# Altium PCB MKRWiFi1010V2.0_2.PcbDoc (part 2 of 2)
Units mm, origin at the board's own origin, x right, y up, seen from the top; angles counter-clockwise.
Board outline 61.5 x 25 mm, 4 copper layers (Top, PWR, MID, Bottom), stack 0.925 mm thick; 118 components, 85 nets, 439 pads, 197 vias.
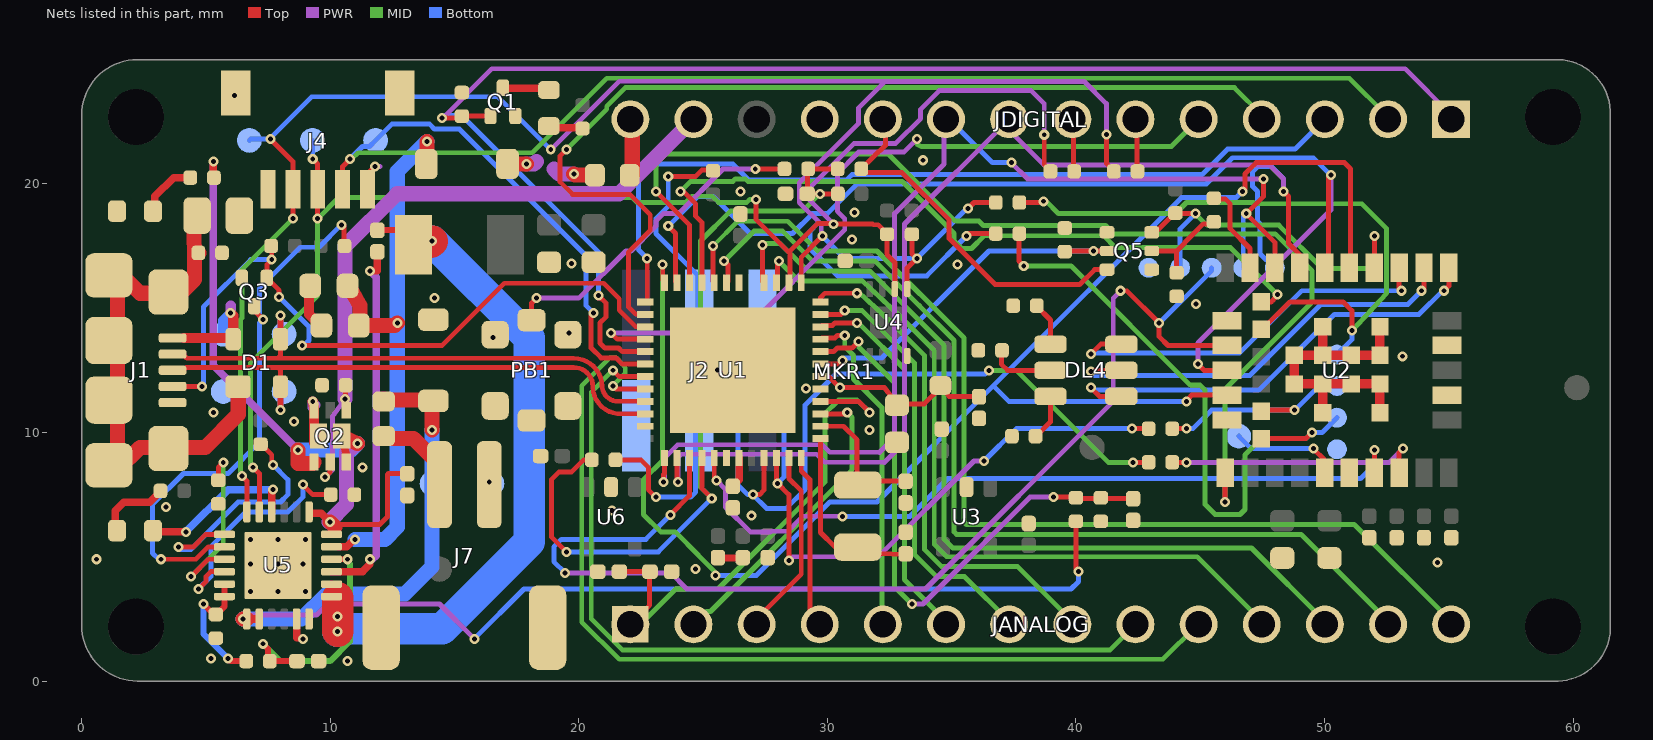
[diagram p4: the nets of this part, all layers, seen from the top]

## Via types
v1: diameter 0.403, hole 0.2, Top to Bottom, tented both sides, 183 vias
v2: diameter 0.398, hole 0.195, Top to Bottom, tented both sides, 14 vias

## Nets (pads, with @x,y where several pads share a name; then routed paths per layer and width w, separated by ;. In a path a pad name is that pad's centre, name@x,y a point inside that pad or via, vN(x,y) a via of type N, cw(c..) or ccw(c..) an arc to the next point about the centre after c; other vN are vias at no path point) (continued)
+5V: D1.4 D3.C F1.2 J1.1 J4.1 Q2.D Q2.D2 VBUS.X | length 10.7
  Top w0.2: J4.1@11.5,19.775 11.5,20.4 v1(11.8,20.7)
  Top w0.406: J1.1@4.125,13.8 5.95,13.8 6.1,13.95 6.1,14.7 v1(6,14.8) ; v2(9.3,11.25) 9.35,11 9.35,10.89 9.35,9.583 Q2.D2@9.533,9.851
  Top w0.61: D3.C@17.105,20.8 v1(17.9,20.8) ; v1(19.8,20.4) 19.85,20.35 F1.2@20.55,20.35
  PWR w0.2: v1(11.8,20.7) v1@12,20.7
  PWR w0.406: v1(6,14.8) 6,15.1 ; v2(9.3,11.25) 9.3,11 v2@9.4,11.1
  PWR w0.61: v1(17.9,20.8) 18.2,20.8 18.3,20.9 ; 19,20.6 19.2,20.4 v1(19.8,20.4)
  Bottom w0.406: VBUS.X@5.7,13.95 5.7,14.5 v1(6,14.8)
GND: BATT-.X C1.2 C2.1 C3.2 C4.2 C5.1 C6.1 C7.1 C8.1 C9.2 C12.1 C13.1 C14.2 C16.2 C17.1 C18.1 C19.1 C20.1 C21.1 C22.1 C23.2 C24.1 C25.2 C26.1 C27.2 C28.2 C29.1 C30.2 C31.1 C32.1 C33.1 D2.A DL3.C GND.X J1.5 J2.5 J4.5 J4.SH1 J4.SH2 J7.2 J7.3 J7.4 JDIGITAL.11 JGND.X MKR1.GND PB1.1 PB1.2 PB1.3 PB1.4 PB1.5 PGND.X Q1.S Q3.S Q5.1 Q5.4 R1.1 R9.1 R10.2 R11.2 R16.1 R19.1 R25.1 R28.2 R29.1 R34.1 R35.1 R36.1 U1.5 U1.18 U1.35 U1.42 U1.49 U2.6 U2.12 U2.14 U2.26 U2.30 U2.GND1 U2.GND2 U2.GND3 U2.GND4 U2.GND5 U2.GND6 U2.GND7 U2.GND8 U2.GND9 U2.GND10 U2.GND11 U2.GND12 U3.2 U4.4 U5.17 U5.18 U5.EXP U6.2 | length 17.2
  Top w0.152: U2.26@45.948,14.627 45.948,14.589 46.037,14.5 U2.26@46.075,14.5
  Top w0.2: v1(19.6,14) 19.625,14.025 PB1.4@19.625,14.075
  Top w0.3: C26.1@25.6,4.951 C24.1@26.6,4.951
  Top w0.305: U5.17@8.65,2.495 8.65,1.75 v1(8.9,1.7)
  Top w0.381: U2.GND7@49.93,10.8 U2.GND8@49.93,11.95 ; U2.GND10@49.93,14.25 U2.GND9@49.93,13.1 ; U2.GND1@52.23,10.8 U2.GND2@52.23,11.95 U2.GND5@51.08,11.95 U2.GND8@49.93,11.95 ; U2.GND4@52.23,14.25 U2.GND3@52.23,13.1 U2.GND6@51.08,13.1 U2.GND9@49.93,13.1 ; U2.GND8@49.93,11.95 U2.GND11@48.78,11.95 U2.GND12@48.78,13.1 U2.GND9@49.93,13.1
  Top w0.406: C13.1@9.25,15.901 9.15,15.801 9.15,14.75 9.6,14.3 C12.1@9.7,14.3
  MID w0.2: 19.4,14.3 19.6,14.1 v1(19.6,14)
  other v1: 10.7,0.8 5.2,0.9 6.8,3.6 7.9,3.6 9,3.6 24.7,4.5 6.8,4.7 7.9,4.7 8.9,4.7 54.535,4.765 0.6,4.9 6.8,5.7 7.9,5.7 9,5.7 26.95,6.65 21.335,6.865 3.4,7 16.4,8 11.3,8.6 31.7,10.1 8.55,10.45 5.3,10.8 29.135,11.765 25.585,12.515 53.135,13.065 16.555,13.815 44.835,15.165 14.2,15.4 35.235,16.765 19.7,16.8 30.985,17.765 31.1,18.85 26.5,19.7 33.85,20.95 6.15,23.55
LED_BLUE: DL4.2 U2.17 | length 17.1
  Top w0.2: v1(40.6,12.45) 40.65,12.5 DL4.2@41.825,12.5 ; v1(53.9,15.7) 54,15.8 U2.17@54,16.625
  Bottom w0.2: v1@40.7,12.35 v1(40.6,12.45) 40.75,12.3 47,12.3 49.85,15.15 53.35,15.15 v1(53.9,15.7)
LED_GREEN: DL4.1 U2.16 | length 18.3
  Top w0.2: v1(40.6,11.8) 40.95,11.45 DL4.1@41.825,11.45 ; v1(54.8,15.7) 55,15.9 U2.16@55,16.625
  Bottom w0.2: v1(40.6,11.8) 40.7,11.7 47.35,11.7 50.4,14.75 53.8,14.75 54.75,15.7 v1(54.8,15.7)
LED_RED: DL4.3 U2.18 | length 15.9
  Top w0.2: v1@40.585,13.135 v1(40.6,13.15) 41,13.55 DL4.3@41.825,13.55 ; U2.18@53,16.625 53,15.8 v1(53.1,15.7)
  Bottom w0.2: v1(40.6,13.15) 40.65,13.2 46.587,13.2 49.088,15.7 v1(53.1,15.7)
NetC1_1: C1.1 D1.1 J1.M1 J1.M2 J1.M3 J1.M4 J1.M5 J1.M6 R1.2 | length 21.2
  Top w0.61: C1.1@4.5,18.725 R1.2@4.55,17.15 ; R1.2@4.725,17.225 R1.2@4.55,17.15 ; D1.1@6.3,11.65 6.3,10.725 4.975,9.4 4,9.4 2.35,9.4 1.45,8.5 1.45,11.3 1.45,13.7 1.45,16.5 2.35,15.6 4,15.6 4.55,16.15 R1.2@4.55,17.15
NetC6_2: C6.2 R8.1 R9.2 U1.8 | length 23.8
  Top w0.2: U1.8@29.725,13.25 30.25,13.25 30.4,13.4 31,13.4 v1(31.25,13.65) ; v1(39.1,7.4) 39.95,7.4 40,7.35 41,7.35 C6.2@42.3,7.35
  PWR w0.2: v1(33.4,3.1) 33.85,3.1 38.15,7.4 v1(39.1,7.4)
  MID w0.2: v1(31.25,13.65) 31.25,13.45 32.7,12 32.7,3.8 v1(33.4,3.1)
NetC14_1: C14.1 Q2.K Q2.K2 Q2.S R27.2 U5.1 U5.24 | length 29
  Top w0.2: U5.1@9.15,6.805 U5.1@9.2,6.755 ; 10.2,6.2 10.3,6.3 10.73,6.3 12,6.3 12.3,6.6 12.3,8.3 12.35,8.35 C14.1@13.1,8.35
  Top w0.3: U5.1@9.2,6.755 9.645,6.755 v1(10,6.4)
  Top w0.305: R27.2@5.3,20.25 v1(5.3,20.9) ; Q2.K2@10.467,9.851 10.65,9.117 Q2.K@10.65,8.81
  Top w0.605: v1(10,6.4) 10.2,6.2
  Top w0.61: v1(8.7,9.3) 8.7,8.75 9.31,8.75 Q2.S@9.35,8.81 ; Q2.K2@10.467,9.851 v1(11.1,9.55)
  PWR w0.305: v1(5.3,20.9) 5.3,12.7 v1(8.7,9.3)
  PWR w0.605: v1(10,6.4) 9.95,6.4 10.65,7.1 10.65,9.2 v1(11.1,9.55)
  Bottom w0.61: v1(8.7,9.3) 10.85,9.3 v1(11.1,9.55)
NetC15_1: C15.1 U5.21 | length 14.8
  Top w0.305: U5.21@10.055,4.4 11.3,4.4 11.6,4.7 v1(11.6,4.9) ; v1(11.6,16.5) 11.9,16.5 C15.1@11.9,17.25
  PWR w0.305: v1(11.6,4.9) 11.7,4.9 11.85,5.05 11.85,16.25 v1(11.6,16.5)
NetC15_2: C15.2 L2.1 U5.19 U5.20 | length 28.4
  Top w0.24: C15.2@11.9,18.15 13.15,18.15 L2.1@13.35,17.55
  Top w0.305: U5.20@10.055,3.9 U5.19@10.055,3.4 10.245,3.4 10.3,3.355 v1(10.3,2.6)
  Top w1.27: v1(10.3,2) U5.19@10.3,3.355 ; L2.1@13.35,17.55 14.05,17.65 v1(14.1,17.7)
  Bottom w1.27: v1(10.3,2) 10.4,2.1 14.5,2.1 18,5.6 18,13.8 v1(14.1,17.7)
NetC16_1: C16.1 R30.1 U5.22 | length 10
  Top w0.24: v1(7.3,1.5) 7.5,1.3 7.5,0.85 7.55,0.8 C16.1@8.65,0.8 ; U5.22@10.055,4.9 v1(10.7,4.9)
  MID w0.24: v1(7.3,1.5) 8,0.8 10,0.8 10.8,1.6 10.8,4.7 10.7,4.8 v1(10.7,4.9)
NetC23_1: C23.1 C27.1 L3.2 U1.6 | length 7.3
  Top w0.2: U1.6@29.725,12.25 30.05,12.25 v1(30.5,11.8) 32.3,11.8 32.8,11.15 33.9,11.15 34.55,11.8 34.9,11.45 C23.1@36.1,11.45
NetC25_1: C25.1 U1.43 | length 1.2
  Top w0.305: C25.1@26.2,7.85 26.45,8.1 U1.43@26.45,8.975
NetDL1_A: DL1.A R15.2 | length 1.4
  Top w0.305: DL1.A@18.8,22.25 R15.2@20.15,22.25
NetDL1_C: DL1.C Q1.D | length 1.9
  Top w0.305: Q1.D@16.95,23.87 16.97,23.85 DL1.C@18.8,23.85
NetDL2_A: DL2.A R23.1 | length 3
  Top w0.305: DL2.A@1.35,6.05 1.35,6.85 1.7,7.2 2.75,7.2 R23.1@3.2,7.65
NetDL3_A: DL3.A R27.1 | length 2.5
  Top w0.305: DL3.A@3.05,18.9 2.95,18.9 2.95,19.5 3.7,20.25 R27.1@4.4,20.25
NetDL4_4: DL4.4 R36.2 | length 1.8
  Top w0.2: R36.2@38.4,15.1 38.975,14.525 DL4.4@38.975,13.55
NetDL4_5: DL4.5 R34.2 | length 2.6
  Top w0.2: R34.2@37,13.3 37,12.75 37.25,12.5 DL4.5@38.975,12.5
NetDL4_6: DL4.6 R35.2 | length 1.8
  Top w0.2: R35.2@38.4,9.85 38.975,10.425 DL4.6@38.975,11.45
NetF1_1: F1.1 JDIGITAL.14 MKR1.5V | length 2.3
  Top w0.61: JDIGITAL.14@22.135,22.66 22.15,22.645 F1.1@22.15,20.35
NetF2_1: F2.1 J7.1 | length 3.5
  Top w0.61: F2.1@12.15,9.75 13.35,9.75 14.4,8.7 J7.1@14.4,7.901
NetJ2_3: J2.3 R2.1 | length 7.2
  Top w0.2: R2.1@21.45,8.9 22.5,8.9 22.8,8.6 22.8,7.7 v1(23.1,7.4)
  Bottom w0.2: v1(23.1,7.4) 24.5,7.4 24.7,7.6 24.7,10.127 J2.3@24.85,10.278
NetJCLK_X: JCLK.X R18.1 U2.35 | length 26.6
  Top w0.2: R18.1@37.7,19.25 38.65,19.25 v1(38.7,19.3) ; U2.35@47.45,14.15 47.5,14.15 48.6,15.25 50.75,15.25 51.1,14.9 v1(51.1,14.1)
  MID w0.2: v1(38.7,19.3) 38.8,19.3 39.3,18.8 44,18.8 44.45,19.25 47.15,19.25 47.2,19.2 51.5,19.2 52.5,18.2 52.5,15.6 v1(51.1,14.1)
  Bottom w0.2: JCLK.X@50.5,13.135 51.1,13.735 v1(51.1,14.1)
NetJDIGITAL_6: JDIGITAL.6 MKR1.11 R31.1 | length 2.2
  Top w0.2: R31.1@42.45,20.5 42.45,22.655 JDIGITAL.6@42.455,22.66
NetJDIGITAL_7: JDIGITAL.7 MKR1.12 R32.1 | length 2.2
  Top w0.2: R32.1@39.9,20.5 39.9,22.645 JDIGITAL.7@39.915,22.66
NetJTDO_X: JTDO.X R22.2 U2.32 | length 8.7
  Top w0.2: R22.2@43.85,10.15 v1(44.45,10.15) ; U2.32@47.45,10.85 47.5,10.9 v1(48.8,10.9)
  Bottom w0.2: v1(44.45,10.15) 44.7,10.15 45.45,10.9 v1(48.8,10.9) 49.765,11.865 JTDO.X@50.5,11.865
NetJTMS_X: JTMS.X R20.1 U2.31 | length 25.9
  Top w0.2: R20.1@37.7,18 37.7,16.9 v1(37.9,16.7) ; U2.31@47.45,9.75 49.25,9.75 v1(49.5,10)
  MID w0.2: v1(37.9,16.7) 39.8,16.7 44.6,11.9 45,11.9 45.2,11.7 45.2,7.1 45.6,6.7 46.6,6.7 46.8,6.9 46.8,9.1 47.45,9.75 49.25,9.75 v1(49.5,10)
  Bottom w0.2: v1(49.5,10) 49.905,10 JTMS.X@50.5,10.595
NetLPO_IN_X: LPO_IN.X U2.5 | length 4.4
  Top w0.2: v1(49.55,9.35) 50,8.9 U2.5@50,8.375
  Bottom w0.2: LPO_IN.X@46.55,9.85 47.05,9.35 v1(49.55,9.35)
NetPB1_6: PB1.6 R3.1 | length 13.2
  Top w0.2: PB1.6@18.1,14.575 18.1,15.2 v1(18.3,15.4) ; v1(27.1,20.6) R3.1@28.3,20.6
  PWR w0.2: v1(18.3,15.4) 20,15.4 21.9,17.3 22.1,17.3 23.1,18.3 23.1,18.5 23.4,18.8 24,18.8 25.8,20.6 v1(27.1,20.6)
NetQ3_D: Q3.D R26.2 U5.8 | length 22.8
  Top w0.2: v1(3.2,4.9) 4.6,4.9 5.1,5.4 U5.8@5.745,5.4 ; Q3.D@6.95,15.081 6.95,14.9 v1(7.3,14.55) ; v1(10.45,18.35) 10.55,18.3 R26.2@10.55,17.5
  Bottom w0.2: v1(3.2,4.9) 3.1,4.9 2.85,5.15 2.85,7.1 4.1,8.35 5.9,8.35 7.15,9.6 7.15,14.4 v1(7.3,14.55) 7.15,14.7 7.15,15.8 8.8,17.45 9.55,17.45 v1(10.45,18.35)
NetQ5_5: Q5.5 R11.1 R17.2 | length 3.9
  Top w0.2: Q5.5@43.05,17.3 44.05,17.3 ; R11.1@44.05,16.4 44.05,17.3 ; R17.2@45.55,18.475 45.468,18.393 45.125,18.393 44.717,17.985 44.383,17.651 44.383,17.633 44.05,17.3
NetQ5_6: Q5.6 R7.1 RST.X U2.19 | length 15.2
  Top w0.2: Q5.6@43.05,18.05 43.2,18.05 R7.1@44,18.85 ; R7.1@43.92,18.77 R7.1@44,18.85 ; v1(44.8,18.8) 44.05,18.8 R7.1@44,18.85 ; U2.19@52,16.625 v1(52,17.9)
  MID w0.2: v1(44.8,18.8) 45.263,18.338 48.162,18.338 49.9,16.6 51.8,16.6 52,16.8 v1(52,17.9)
  Bottom w0.2: RST.X@44.19,16.625 44.19,18.19 v1(44.8,18.8)
NetR12_2: R12.2 U2.8 | length 10.6
  Top w0.2: R12.2@43.85,8.8 v1(44.45,8.8) ; U2.8@53,8.375 53,9.2 v1(53.15,9.35)
  PWR w0.2: v1(44.45,8.8) 52.6,8.8 v1(53.15,9.35)
NetR17_1: R17.1 U2.24 | length 3.6
  Top w0.2: R17.1@45.55,19.4 46,19.4 46.2,19.2 46.2,18.2 47,17.4 U2.24@47,16.625
NetR24_2: R24.2 U5.7 | length 10
  Top w0.2: v1(3.9,5.4) 4.5,5.4 5,5.9 U5.7@5.745,5.9 ; R24.2@7.2,9.55 7.65,9.1 7.65,8.75 v1(7.7,8.7)
  Bottom w0.19: v1(7.7,8.7) v1@7.75,8.75
  Bottom w0.2: v1(3.9,5.4) 4,5.3 4.4,5.3 6.3,7.2 8,7.2 8.3,7.5 8.3,8.1 v1(7.7,8.7)
NetR25_2: R25.2 U5.9 | length 7.6
  Top w0.2: v1(4.4,4.2) 5.1,4.9 U5.9@5.745,4.9 ; R25.2@5.5,8.05 5.5,8.6 v1(5.7,8.8)
  MID w0.2: v1(4.4,4.2) 5.7,5.5 v1(5.7,8.8)
NetR28_1: R28.1 U5.10 | length 9.7
  Top w0.2: v1(4.7,3.7) 5,4 5,4.2 5.2,4.4 U5.10@5.745,4.4 ; v1(8.9,7.9) 9.3,7.5 R28.1@10.05,7.5
  Bottom w0.2: v1(4.7,3.7) 5.2,4.2 5.2,5.4 6.6,6.8 8.3,6.8 8.9,7.4 v1(8.9,7.9)
NetR29_2: R29.2 R30.2 U5.11 U5.12 | length 5.5
  Top w0.24: v1(4.9,3.1) 5.35,2.65 5.4,2.65 5.745,2.995 U5.12@5.745,3.4 U5.11@5.745,3.9 ; v1(5.9,0.9) 6,0.8 R30.2@6.65,0.8
  Bottom w0.24: v1(4.9,3.1) 4.9,1.9 v1(5.9,0.9)
PA00_XIN32: C3.1 U1.1 Y1.2 | length 7.5
  Top w0.2: U1.1@29.725,9.75 29.725,5.975 30.3,5.4 31.213,5.4 Y1.2@31.225,5.387 31.462,5.15 C3.1@33.15,5.1
PA01_XOUT32: C4.1 U1.2 Y1.1 | length 5.5
  Top w0.2: U1.2@29.725,10.25 30.65,10.25 31.2,9.7 31.2,8.612 Y1.1@31.225,7.887 31.388,8.05 C4.1@33.15,8.05
PA02_AIN0: JANALOG.2 MKR1.A0 U1.3 | length 12.4
  Top w0.2: U1.3@29.725,10.75 30.75,10.75 v1(30.8,10.8)
  MID w0.2: JANALOG.2@24.675,2.34 25.135,2.8 25.3,2.8 31,8.5 31,10.6 v1(30.8,10.8)
PA03_VREFA: C5.2 C7.2 JANALOG.1 MKR1.AREF U1.4 | length 20.8
  Top w0.2: C7.2@21.65,4.4 22.85,4.4 22.85,3.055 JANALOG.1@22.135,2.34 ; U1.4@29.725,11.25 31.25,11.25 v1(31.7,10.8)
  MID w0.2: JANALOG.1@22.135,2.34 22.2,2.405 22.605,2.405 23.9,3.7 25.6,3.7 29.9,8 29.9,10.75 30.45,11.3 31.2,11.3 v1(31.7,10.8)
PA04_AIN4: JANALOG.5 MKR1.A3 U1.9 | length 13.3
  Top w0.2: U1.9@29.725,13.75 29.775,13.8 30.3,13.8 30.4,13.9 v1(30.7,13.9)
  MID w0.2: v1(30.7,13.9) 30.7,13.45 31.05,13.1 31.05,12.15 32.2,11 32.2,2.4 32.205,2.395 32.295,2.395 JANALOG.5@32.295,2.34
PA05_AIN5: JANALOG.6 MKR1.A4 U1.10 | length 15.2
  Top w0.2: U1.10@29.725,14.25 29.775,14.3 30.2,14.3 30.3,14.4 v1(31.2,14.4)
  MID w0.2: v1(31.2,14.4) 31.3,14.4 31.3,14.35 33.1,12.55 33.1,4.075 JANALOG.6@34.835,2.34
PA06_AIN6: JANALOG.7 MKR1.A5 U1.11 | length 17.4
  Top w0.2: U1.11@29.725,14.75 30.55,14.75 v1(30.7,14.9)
  MID w0.2: v1(30.7,14.9) 31.4,14.9 33.5,12.8 33.5,5.1 34.4,4.2 35.515,4.2 JANALOG.7@37.375,2.34
PA07_AIN7: JANALOG.8 MKR1.A6 U1.12 | length 20.5
  Top w0.2: U1.12@29.725,15.25 29.725,15.425 29.9,15.6 v1(31.2,15.6)
  MID w0.2: v1(31.2,15.6) 31.3,15.6 32.5,14.5 33.9,13.1 33.9,5.3 34.6,4.6 37.655,4.6 JANALOG.8@39.915,2.34
PA08_S0_I2C_SDA: ESDA.X J4.4 R14.1 R18.2 R31.2 U1.13 U4.5 U5.6 | length 77.7
  Top w0.2: v1(6.45,8.25) 6.65,8.05 U5.6@6.65,6.805 ; v1(7.6,21.8) 8.5,20.9 v1(8.5,18.6) ; U1.13@28.95,16.025 28.95,17.05 v1(29.8,17.9) ; U4.5@33.213,15.95 33.213,16.613 v1(33.6,17) ; R14.1@33.4,18.05 33.4,17.2 v1(33.6,17) ; v1@33.613,16.988 v1(33.6,17) ; v1(35.65,19) 35.9,19.25 R18.2@36.8,19.25 ; v1(41.225,21.988) 41.225,20.825 R31.2@41.55,20.5
  PWR w0.19: v2(18.875,21.375) 21.625,24.125 32.25,24.125 32.263,24.062 ; v1(29.8,17.9) 29.75,18 29.75,18.375 28.875,19.25 28.875,20.045 31.25,22.42 31.25,23.05 32.263,24.062 ; 32.325,24.125 32.263,24.062
  PWR w0.2: 32.325,24.125 40.325,24.125 41.225,23.225 v1(41.225,21.988)
  MID w0.2: v1(6.45,8.25) 6.4,8.3 6.4,14.55 6.45,14.6 6.45,16.55 v1(8.5,18.6)
  Bottom w0.19: v1(7.6,21.8) 7.625,21.875 9.25,23.5 16.75,23.5 v2(18.875,21.375)
  Bottom w0.2: ESDA.X@6.75,21.75 6.8,21.8 v1(7.6,21.8) ; v1(29.8,17.9) 30.7,17 v1(33.6,17) 35.6,19 v1(35.65,19)
PA09_S0_I2C_SCL: ESCL.X J4.3 R13.1 R20.2 R32.2 U1.14 U4.6 U5.5 | length 72.1
  Top w0.19: v2@27.125,19.25 v2(27.125,19.375) ; v2@30.25,18.4 v2(30.25,18.375) 30.26,18.385 31.83,18.385 31.858,18.357 32.043,18.357 32.35,18.05 R13.1@32.4,18.05
  Top w0.2: v1(6.9,8.6) 7.15,8.35 U5.5@7.15,6.805 ; v1(9.3,21) 9.5,20.8 v1(9.5,18.6) ; v2@27.125,19.25 27.125,18.575 28.45,17.25 ; v2@30.25,18.4 29.6,18.4 28.45,17.25 ; R13.1@32.4,18.05 32.4,17.15 32.712,16.837 U4.6@32.712,15.95 ; v1(35.6,17.9) 35.7,18 R20.2@36.8,18 ; v1(38.725,21.975) 38.725,20.775 R32.2@39,20.5 ; 28.45,17.25 28.5,17.2 U1.14@28.5,16.075 ; U1.14@28.5,16.075 U1.14@28.45,16.025 28.475,16.025 28.5,16.05 U1.14@28.5,16.075
  PWR w0.19: v2(30.25,18.375) 29.25,19.375 29.25,19.8 31.075,21.625 32.75,21.625 33.75,22.625 33.75,23 34.5,23.75
  PWR w0.2: 34.5,23.75 38.2,23.75 38.725,23.225 v1(38.725,21.975)
  MID w0.19: 24.55,19.5 25.375,19.5 25.625,19.25 26.75,19.25 26.875,19.375 v2(27.125,19.375)
  MID w0.2: v1(6.9,8.6) 6.8,8.7 6.8,12.8 9.5,15.5 v1(9.5,18.6) 10.35,19.45 22.15,19.45 22.35,19.25 24.3,19.25 24.55,19.5
  Bottom w0.2: ESCL.X@9.29,21.75 9.3,21.74 v1(9.3,21) ; v2(30.25,18.375) 30.225,18.4 29.6,18.4 29.3,18.1 29.3,17.4 30.4,16.3 34,16.3 v1(35.6,17.9)
PA10_TCC0-W2: JANALOG.11 MKR1.2 U1.15 | length 31.1
  Top w0.2: U1.15@27.95,16.025 28,16.075 28,16.85 v1(28.05,16.9)
  PWR w0.2: JANALOG.11@47.5,2.375 JANALOG.11@47.535,2.34
  MID w0.2: v1(28.05,16.9) 28.85,16.1 31.4,16.1 32.9,14.7 34.3,13.3 34.3,5.5 34.8,5 44.875,5 47.535,2.34 JANALOG.11@47.5,2.375
PA11_TCC0-W3: JANALOG.12 MKR1.3 U1.16 | length 35.1
  Top w0.2: v1(27.4,17.55) 27.4,16.075 U1.16@27.45,16.025
  MID w0.2: v1(27.4,17.55) 27.5,17.6 28.1,17.6 29.2,16.5 31.7,16.5 34.7,13.5 34.7,5.7 35.05,5.35 47.065,5.35 JANALOG.12@50.075,2.34
PA12_S2_TX/MOSI: U1.21 U2.36 | length 31.6
  Top w0.2: v1(24.1,19.7) 24.2,19.7 24.7,19.2 24.7,18.7 24.95,18.45 U1.21@24.95,16.025 ; U2.36@47.45,15.25 47.85,15.25 47.9,15.3 v1(48.1,15.55)
  MID w0.2: v1(24.1,19.7) 24.5,20.1 26.2,20.1 26.3,20.2 26.7,20.2 26.8,20.1 33,20.1 35.1,18 35.1,17.7 35.4,17.4 35.8,17.4 36.313,17.913 41.112,17.913 41.587,17.438 46.213,17.438 v1(48.1,15.55)
PA13_S2_RX/MISO: U1.22 U2.1 | length 45.8
  Top w0.2: v1(23.1,19.7) 24.45,18.35 U1.22@24.45,16.025 ; v1(46,7.2) U2.1@46,8.375
  MID w0.2: v1(23.1,19.7) 23.1,20.8 23.5,21.2 32.45,21.2 35.15,18.5 36.1,18.5 36.275,18.325 41.188,18.325 41.525,17.988 48.013,17.988 49.5,16.5 49.5,15.25 46,11.75 v1(46,7.2)
PA14_S2_RTS/CS: U1.23 U2.21 U2.28 | length 46.7
  Top w0.2: v1(23.6,18.3) 23.9,18 23.9,16.075 U1.23@23.95,16.025 ; v1(44.9,12.75) 45.15,12.5 U2.28@46.075,12.5 ; U2.21@50,16.625 50.15,16.775 50.15,20.25 v1(50.25,20.35)
  PWR w0.2: v1(44.9,12.75) 44.9,13.6 50.25,18.95 v1(50.25,20.35)
  Bottom w0.2: v1(23.6,18.3) 24.8,19.5 25.4,19.5 26.9,18 28.6,18 29.4,18.8 30,18.8 31.2,20 45.25,20 46.3,21.05 49.55,21.05 v1(50.25,20.35)
PA15_S2_CTS/SCK: U1.24 U2.20 U2.29 | length 61.8
  Top w0.19: v2(23.375,16.75) 23.375,16.125 U1.24@23.45,16.025
  Top w0.2: v1(44.45,11.25) 44.65,11.5 U2.29@46.075,11.5 ; v1(46.7,19.7) 46.8,19.8 46.8,20.4 47.25,20.85 50.8,20.85 51.05,20.6 51.05,16.675 U2.20@51,16.625
  MID w0.19: 24.825,5.05 25.5,4.375 v2(25.5,4.25)
  MID w0.2: v2(23.375,16.75) 23.375,8.875 22.6,8.1 22.6,6.7 23.3,6 23.875,6 24.825,5.05
  Bottom w0.2: v2(25.5,4.25) 27.15,4.25 30.1,7.2 32,7.2 36.675,11.875 ; v1(44.45,11.25) 37.3,11.25 36.675,11.875 ; v1(46.7,19.7) 46.45,19.45 44.25,19.45 36.675,11.875
PA16_S1_MOSI: JDIGITAL.3 MKR1.8 U1.25 | length 34.5
  Top w0.19: U1.25@22.675,15.25 22.75,15.25 v2(22.75,17)
  PWR w0.19: JDIGITAL.3@50,22.625 JDIGITAL.3@50.075,22.66
  Bottom w0.19: 30.75,20.15 31,20.375
  Bottom w0.2: v2(22.75,17) 22.4,17.35 22.4,20.2 23,20.8 26.2,20.8 26.85,20.15 30.75,20.15 ; 31,20.375 45.075,20.375 46.1,21.4 48.815,21.4 JDIGITAL.3@50.075,22.66
PA17_S1_SCK: JDIGITAL.4 MKR1.9 U1.26 | length 40.1
  Top w0.19: v2(19.5,21.375) 19.25,21.125 19.25,20.075 19.75,19.575 22.05,19.575 22.875,18.75 22.875,18.125 22,17.25 22,15.05 22.3,14.75 U1.26@22.675,14.75
  MID w0.19: v2(19.5,21.375) 21.125,23 21.125,23.125 21.875,23.875 46.375,23.875 47.5,22.75 JDIGITAL.4@47.535,22.66
PA18_OTG: J1.4 Q3.G R21.2 U1.27 | length 28.4
  Top w0.19: v2(8.875,13.5) 14.5,13.5 17,16 21,16 21.625,15.375 21.625,14.925 22.3,14.25 U1.27@22.675,14.25
  Top w0.2: J1.4@4.125,11.85 4.886,11.855 v1(4.849,11.847) ; R21.2@7.65,17.5 v1(7.65,16.95) 7.45,16.75 Q3.G@7.45,16.221 7.95,15.72 v1(7.95,15.45)
  Bottom w0.19: v1@4.824,11.822 v1(4.849,11.847)
  Bottom w0.2: v1(4.849,11.847) 4.897,11.847 4.9,11.85 4.899,12.743 4.899,15.049 6.8,16.95 v1(7.65,16.95) ; v1(7.95,15.45) 9.15,14.25 9.15,13.7 8.95,13.5 v2(8.875,13.5) v2@8.9,13.5
PA19_S1_MISO: JDIGITAL.5 MKR1.10 U1.28 | length 30.9
  Top w0.2: v1(21.3,14) 21.55,13.75 U1.28@22.675,13.75
  PWR w0.2: v1(21.3,14) 26.55,14 30.7,18.15 30.7,18.6 30.4,18.9 30.4,20.4 31.25,21.275 33.075,21.275 v1(33.6,21.8)
  MID w0.2: v1(33.6,21.8) 33.6,21.6 33.8,21.5 43.835,21.5 JDIGITAL.5@44.995,22.66
PA20_TCC0-W6: JDIGITAL.1 MKR1.6 Q1.G R16.2 U1.29 | length 58.9
  Top w0.2: v1(14.5,22.65) 15.25,22.65 15.3,22.75 15.32,22.73 Q1.G@16.45,22.73 ; v1@20.8,15.4 v1(20.8,15.5) 20.85,15.45 21.1,15.2 21.1,14.65 20.85,14.4 20.85,13.6 21.05,13.4 21.6,13.4 21.75,13.25 U1.29@22.675,13.25
  PWR w0.19: v1(14.5,22.65) 14.5,22.625 16.5,24.625 53.25,24.625 55.125,22.75 JDIGITAL.1@55.155,22.66
  Bottom w0.2: v1(14.5,22.65) 14.6,22.75 15.3,22.75 20.8,17.25 v1(20.8,15.5)
PA21_TCC0-W7: EWK.X J4.2 JDIGITAL.2 MKR1.7 U1.30 | length 63.7
  Top w0.2: J4.2@10.5,19.775 10.5,20.7 v1(10.8,21) ; v1(20.6,14.8) 20.5,14.7 20.5,13.4 20.9,13 21.5,13 21.75,12.75 U1.30@22.675,12.75
  MID w0.19: v1(10.8,21) 10.875,21 11.125,21.25 18.125,21.25 21.125,24.25 51,24.25 52.5,22.75 JDIGITAL.2@52.615,22.66
  Bottom w0.2: v1(10.8,21) 11.3,21.5 11.58,21.5 11.83,21.75 12.48,22.4 14,22.4 14.2,22.2 15.2,22.2 20.3,17.1 20.3,15.1 v1(20.6,14.8)
PA22_TC4-W0: JANALOG.9 MKR1.0 U1.31 | length 34.7
  Top w0.19: v2(21.375,12.5) 21.625,12.25 U1.31@22.675,12.25
  MID w0.19: v2(21.375,12.5) 20.5,11.625 20.5,2.5 21.75,1.25 41.375,1.25 42.375,2.25 JANALOG.9@42.455,2.34
PA23_TC4-W1: JANALOG.10 MKR1.1 U1.32 | length 40.3
  Top w0.19: v2(21.375,11.875) 21.5,11.75 U1.32@22.675,11.75
  MID w0.19: v2(21.375,11.875) 21.875,12.375 21.875,12.625 21.5,13 21.25,13 20.125,11.875 20.125,2.375 21.625,0.875 43.5,0.875 44.875,2.25 JANALOG.10@44.995,2.34
PA27_GPIO0: GPIO0.X U1.39 U2.27 | length 47.8
  Top w0.2: v1(23.688,6.688) 24.45,7.45 U1.39@24.45,8.975 ; v1(41.8,15.7) 42.05,15.7 v1(43.35,14.4) ; v1@43.3,14.45 v1(43.35,14.4) ; U2.27@46.075,13.5 43.7,13.5 43.35,13.85 v1(43.35,14.4)
  PWR w0.2: v1(19.45,4.35) 23.7,4.35 24.35,3.7 33.95,3.7 41.5,11.25 41.5,15.4 v1(41.8,15.7) ; v1@43.3,14.45 v1(43.35,14.4)
  Bottom w0.2: v1(19.45,4.35) 19,4.8 19,5.4 19.3,5.7 22.7,5.7 v1(23.688,6.688) ; v1(43.35,14.4) 45.46,16.51 GPIO0.X@45.46,16.625
PA28_ACK: U1.41 U2.7 | length 31.3
  Top w0.19: U1.41@25.45,8.975 25.45,8.175 v1(25.55,8.075)
  Top w0.2: U2.7@52,8.375 v1(52,9.3)
  PWR w0.19: v1(25.55,8.075) 25.9,7.725 25.9,7.125 ; 27.025,6 27.725,6 27.75,6.025 28.4,6.025 29,6.625 v1(30.6,6.625)
  PWR w0.2: 25.9,7.125 25.9,7 26.9,6 27.025,6
  Bottom w0.2: v1(30.6,6.625) 33.325,6.625 34.85,8.15 51.45,8.15 52,8.7 v1(52,9.3)
PA30_SWCLK: J2.4 R4.1 R12.1 U1.45 | length 40.5
  Top w0.19: 27.275,7.5 27.45,7.675 U1.45@27.45,8.975
  Top w0.2: v1(23.6,20.3) 24.7,20.3 24.95,20.55 R4.1@25.4,20.55 ; v1(27,7.5) 27.275,7.5 ; v1(42.3,8.8) R12.1@42.95,8.8
  MID w0.2: v1(36.5,12.5) 37.6,12.5 41.3,8.8 v1(42.3,8.8)
  Bottom w0.2: v1(23.6,20.3) 23.6,19.1 23.1,18.6 23.1,18 24.8,16.3 24.8,14.772 24.85,14.723 26.4,13.172 26.4,7.9 26.8,7.5 v1(27,7.5) 27.55,6.95 28.35,6.95 29.1,7.7 29.1,11.1 30.35,12.35 36.35,12.35 v1(36.5,12.5)
PA31_SWDIO: J2.2 R22.1 U1.46 | length 28.3
  Top w0.2: U1.46@27.95,8.975 27.95,7.95 v1(28,7.95) 28.45,7.5 v1(28.45,4.85) ; v1(42.25,10.15) R22.1@42.95,10.15
  PWR w0.2: v1(28.45,4.85) 28.6,5 32.05,5 35.9,8.85 v1(36.3,8.85)
  Bottom w0.2: J2.2@27.39,14.723 28.25,13.863 28.25,8.2 v1(28,7.95) ; v1(36.3,8.85) 37.6,10.15 v1(42.25,10.15)
PB02_AIN10: JANALOG.3 MKR1.A1 U1.47 | length 7.6
  Top w0.2: JANALOG.3@27.215,2.34 27.215,2.565 28.95,4.3 28.95,7.65 28.45,8.15 U1.47@28.45,8.975
PB03_AIN11: JANALOG.4 MKR1.A2 U1.48 | length 7
  Top w0.2: U1.48@28.95,8.975 28.95,8.45 29.3,8.1 29.3,2.795 JANALOG.4@29.755,2.34
PB08_RST: Q5.2 R10.1 U1.7 | length 14.6
  Top w0.2: U1.7@29.725,12.75 30.45,12.75 v1(30.6,12.9) ; R10.1@39.55,17.3 v1(40.7,17.3) Q5.2@41.25,17.3
  Bottom w0.2: v1(30.6,12.9) 30.7,13 32.2,13 36.5,17.3 v1(40.7,17.3)
PB10_TCC0-W4: JANALOG.13 MKR1.4 U1.19 | length 39.3
  Top w0.19: U1.19@25.95,16.025 U1.19@26,16.075
  Top w0.2: v1(25.85,16.9) 26,16.75 U1.19@26,16.075
  MID w0.19: 27.2,18.1 28.2,18.1 29.4,16.9 31.9,16.9 33.7,15.1
  MID w0.2: v1(25.85,16.9) 27.05,18.1 27.2,18.1 ; 33.7,15.1 35.1,13.7 35.1,6 35.2,5.9 49.055,5.9 JANALOG.13@52.615,2.34
PB11_TCC0-W5: JANALOG.14 MKR1.5 U1.20 | length 42.7
  Top w0.19: v1(25.4,17.5) 25.4,16.075 U1.20@25.45,16.025
  MID w0.19: v1(25.4,17.5) 26.4,18.5 28.4,18.5 29.6,17.3
  MID w0.2: 29.6,17.3 32,17.3 35.5,13.8 35.5,6.4 35.6,6.3 51.195,6.3 JANALOG.14@55.155,2.34
PB22_S5_TX: JDIGITAL.9 MKR1.14 RXD.X U1.37 U2.23 | length 45.9
  Top w0.2: v1(23.4,8) 23.4,8.3 23.45,8.35 U1.37@23.45,8.975 ; v1(47.55,20.2) 47.55,19.5 v1(46.85,18.8) 48,17.65 U2.23@48,16.625
  PWR w0.19: v1(23.4,8) 23.45,8.05 23.45,8.975 23.975,9.5 29.8,9.5 30.1,9.2 32.1,9.2
  PWR w0.2: 32.1,9.2 32.7,9.8 32.7,18.8 34.7,20.8 34.7,22.525 JDIGITAL.9@34.835,22.66 ; v1(37.4,20.85) 38.05,20.2 v1(47.55,20.2)
  Bottom w0.2: JDIGITAL.9@34.835,22.66 36.645,20.85 v1(37.4,20.85) ; RXD.X@46.73,16.625 46.73,18.68 v1(46.85,18.8)
PB23_S5_RX: JDIGITAL.8 MKR1.13 TXD.X U1.38 U2.22 | length 49
  Top w0.2: U1.38@23.95,8.975 23.95,8.05 v1(24,8) ; v1(48.35,19.7) 48.55,19.5 48.55,17.6 49,17.15 U2.22@49,16.625
  PWR w0.19: v1(24,8) 24,9 24.125,9.125 29.575,9.125 29.9,8.8 32.3,8.8
  PWR w0.2: 32.3,8.8 33.1,9.6 33.1,18.385 37.375,22.66 37.375,22.1 38.725,20.75 47.8,20.75 48.35,20.2 v1(48.35,19.7)
  Bottom w0.2: TXD.X@48,16.625 48.025,16.65 47.95,16.65 47.4,17.2 47.4,18.4 47.3,18.5 47.3,19.7 47.1,19.9 47.1,20.5 47.3,20.7 47.85,20.7 48.35,20.2 v1(48.35,19.7)
RESET#: JDIGITAL.10 MKR1.RST Q5.3 R6.2 | length 15
  Top w0.2: JDIGITAL.10@32.338,22.617 32.338,21.55 31.338,20.6 31.488,20.45 33,20.45 34.9,18.55 34.9,17.8 36.75,15.95 40.15,15.95 40.75,16.55 Q5.3@41.25,16.55
  Top w0.305: JDIGITAL.10@32.295,22.66 JDIGITAL.10@32.338,22.617
RESETN: C2.2 R2.2 R3.2 R5.1 R6.1 U1.40 | length 33.3
  Top w0.2: v1(19.5,5.2) 18.9,5.8 18.9,8.1 19.2,8.4 19.7,8.4 20.2,8.9 R2.2@20.55,8.9 ; U1.40@24.95,8.975 24.95,7.75 v1(25.35,7.35) ; R6.1@30.438,20.6 29.2,20.6 29.2,19.6 v1(29.7,19.6) R5.1@30.45,19.6
  MID w0.2: v1(25.35,7.35) 24.9,7.8 24.9,17.7 26.1,18.9 29,18.9 v1(29.7,19.6)
  Bottom w0.2: v1(19.5,5.2) 23.2,5.2 v1(25.35,7.35)
STAT: DL2.C U5.4 | length 6.5
  Top w0.305: DL2.C@3,6.1 2.95,6.05 3,6 v1(4.2,6) ; U5.4@7.65,6.805 7.65,7.65 v1(7.7,7.7)
  Bottom w0.305: v1(4.2,6) 5.9,7.7 v1(7.7,7.7)
USB_N: D1.3 D-.X J1.2 U1.33 | length 22.6
  Top w0.19: J1.2@4.125,13.15 ccw(c4.292,13.15) 4.292,12.983 7.9,12.983 ; D1.3@8,13.8 8,13.084 7.9,12.983 ; U1.33@22.675,11.25 21.583,11.25 cw(c21.583,11.9) 20.933,11.9 20.933,11.85 ccw(c19.8,11.85) 19.8,12.983 7.9,12.983
  Top w0.24: D1.3@8,13.8 8.075,13.875 8.15,13.95 8,13.95 v2(8,14.7)
  Bottom w0.19: D-.X@8.15,13.95 D-.X@8.2,14
  Bottom w0.24: v2(8,14.7) 8,14.1 D-.X@8.15,13.95
USB_P: D1.2 D+.X J1.3 U1.34 | length 22.5
  Top w0.19: J1.3@4.125,12.5 cw(c4.241,12.5) 4.242,12.616 7.9,12.616 ; D1.2@8,11.65 8,12.517 7.9,12.616 ; U1.34@22.675,10.75 21.716,10.75 cw(c21.666,11.85) 20.566,11.8 20.566,11.85 ccw(c19.8,11.85) 19.8,12.616 7.9,12.616
  Top w0.24: v2(8,10.9) D1.2@8,11.65
  Bottom w0.24: v2(8,10.9) 8,11.6 D+.X@8.15,11.65 D+.X@8,11.5
VBATT: BATT+.X D2.C F2.2 R8.2 U5.13 U5.14 | length 55.7
  Top w0.2: R8.2@40,6.45 40,4.5 v1(40.1,4.4)
  Top w0.305: U5.13@6.65,2.495 U5.14@7.15,2.495
  Top w0.61: v1(6.5,2.5) 6.505,2.495 U5.13@6.65,2.495 ; F2.2@12.15,11.35 12.2,11.3 14.15,11.3 14.1,11.25 v1(14.1,10.1)
  PWR w0.2: v1(6.5,2.5) 6.505,2.495 6.65,2.495 6.805,2.65 9.45,2.65 9.9,3.1 14.4,3.1 v1(15.8,1.7)
  Bottom w0.2: v1(15.8,1.7) 17.8,3.7 39.8,3.7 40.1,4 v1(40.1,4.4)
  Bottom w0.61: v1(6.5,2.5) 8.85,2.5 9.875,3.5 13,3.5 14.1,4.6 BATT+.X@14.1,7.945 v1(14.1,10.1)
VIN: JDIGITAL.13 MKR1.VIN Q2.A Q2.G R19.2 | length 27.8
  Top w0.2: v1(9.8,8.2) 10,8.4 Q2.G@10,8.81 ; v1(10.6,11.35) Q2.A@10.65,11.1 ; R19.2@10.6,11.9 Q2.A@10.65,11.1 ; Q2.A@10.65,10.89 Q2.A@10.65,11.1
  PWR w0.2: v1(9.8,8.2) 10.1,8.5 10.1,10.65 v1(10.6,11.35)
  PWR w0.61: v1(10.6,11.35) 10.6,17.5 12.7,19.6 21.615,19.6 24.675,22.66 JDIGITAL.13@24.7,22.635
VUSB1: C12.2 C13.2 D3.A U5.23 | length 22.9
  Top w0.305: U5.23@10.327,5.402 10.676,5.402 10.973,5.7 v1(11,5.7)
  Top w0.61: C13.2@10.75,15.9 11.2,15.1 11.2,14.3 12.6,14.3 v1(12.7,14.4) ; D3.A@13.895,20.8 13.9,20.805 v1(13.9,21.7)
  Bottom w0.61: v1(11,5.7) 12.2,5.7 12.7,6.2 v1(12.7,14.4) 12.7,20.5 v1(13.9,21.7)
pads on no net: FD1.1 FD2.1 FD3.1 J2.6 MKR1.MH1 MKR1.MH2 MKR1.MH3 MKR1.MH4 Q2.NC U2.2 U2.3 U2.4 U2.11 U2.13 U2.15 U2.25 U2.33 U2.34 U3.4 U4.1 U4.2 U4.3 U4.7 U4.9 U5.2 U5.3 U6.4

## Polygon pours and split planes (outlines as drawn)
+5V on PWR "Polygon_1_Net_+5V" (solid, remove dead copper, pour order 1): 23.427,25.127 4.323,25.127 4.323,22.7 cw(c2.3,22.7) 2.3,20.677 -0.127,20.677 -0.127,7.673 11.327,7.673 11.327,19.373 23.427,19.373
+3V3 on PWR "Polygon_1_Net_+3V3" (solid, remove dead copper, pour order 0): 25.925,25.128 25.925,21.375 23.725,21.375 23.725,17.902 23.748,17.925 22.575,17.925 22.575,7.575 34.625,7.575 34.625,21.325 28.525,21.325 28.525,25.072
+3V3D on PWR "Polygon_1_Net_+3V3D" (solid, remove dead copper, pour order 3): 34.975,21.425 34.975,7.575 38.075,7.575 38.075,3.775 55.625,3.775 55.625,16.825 50.252,16.825 49.052,18.025 47.252,18.025 43.852,21.425
+3V8 on PWR "Polygon_1_Net_+3V8" (solid, remove dead copper, pour order 2): 9.473,7.327 11.573,7.327 11.573,19.127 22.327,19.127 22.327,7.227 37.727,7.227 37.727,3.873 20.127,3.873 20.127,-0.127 7.373,-0.127 7.373,3.027 9.473,3.027
GND on MID "Polygon_3_Net_GND" (solid, remove dead copper, pour order 4): -0.127,20.677 2.4,20.677 ccw(c2.4,22.6) 4.323,22.6 4.323,25.127 21.127,25.127 21.127,21.427 28.173,21.427 28.173,25.127 31.377,25.127 31.377,21.427 43.954,21.427 47.254,18.027 49.053,18.027 50.253,16.827 55.627,16.827 55.627,3.573 21.127,3.573 21.127,-0.127 4.373,-0.127 4.373,2.1 ccw(c2.1,2.1) 2.1,4.373 -0.127,4.373
GND on Top "Polygon_2_Net_GND" (solid, remove dead copper, pour order 5): -0.127,-0.228 -0.127,25.027 28.5,25.127 55.927,25.227 55.927,-0.026
GND on Bottom "Polygon_1_Net_GND" (solid, remove dead copper, pour order 6): -0.127,-0.127 -0.127,25.127 43.927,25.127 43.927,21.253 47.153,18.027 49.053,18.027 50.253,16.827 61.627,16.827 61.627,-0.127

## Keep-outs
Top:
  circle w0.254: c59.25,22.75 r2.228
  circle w0.254: c2.25,22.75 r2.228
  circle w0.254: c59.25,2.25 r2.228
  circle w0.254: c2.25,2.25 r2.228
  lines w0.2: 43.8,21.3 47.2,17.9 49,17.9 50.2,16.7 57.4,16.7
  lines w0.254: 0,4.5 2.25,4.5 ; 0,20.55 2.15,20.55 ; 4.45,22.75 4.45,25 ; 4.5,0 4.5,2.25 ; 21,0 21,3.7 57.337,3.787 ; 55.927,11.101 55.927,14.1 ; 57,22.8 57,25 ; 57.32,-0.012 57.32,2.237 ; 57.337,-0.012 57.337,3.587 ; 57.337,21.35 57.337,25 ; 59.22,4.48 59.22,4.49 ; 28.3,25 21,25 21,21.3 28.3,21.3 28.3,25 ; 28.3,25 31.25,25 ; 31.25,25 57.337,25 ; 31.25,25 31.3,21.3 43.8,21.3 57.337,21.3 57.337,25
  lines w0.61: 2.8,10.2 2.8,14.9
Bottom:
  circle w0.254: c59.25,22.75 r2.228
  circle w0.254: c59.25,2.25 r2.228
  circle w0.254: c2.25,22.75 r2.228
  circle w0.254: c2.25,2.25 r2.228
  lines w0.254: 0,4.5 2.25,4.5 ; 0,20.55 2.15,20.55 ; 4.45,22.75 4.45,25 ; 4.5,0 4.5,2.25 ; 21,0 21,3.7 57.337,3.787 ; 57.32,0.05 57.32,2.3 ; 28.3,25 21,25 21,21.3 28.25,21.3 28.3,25 ; 28.3,25 31.25,25 ; 31.25,25 57.337,25 ; 31.25,25 31.3,21.3 57.337,21.3 ; 57.337,3.787 57.337,-0.025 57.337,3.787 ; 57.337,21.3 57.337,25 ; 57.337,21.3 57.337,25
Keep-Out Layer:
  the board outline again, w0.01

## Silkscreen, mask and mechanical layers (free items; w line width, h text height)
Top 3D Body:
  the board outline again, w0.01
